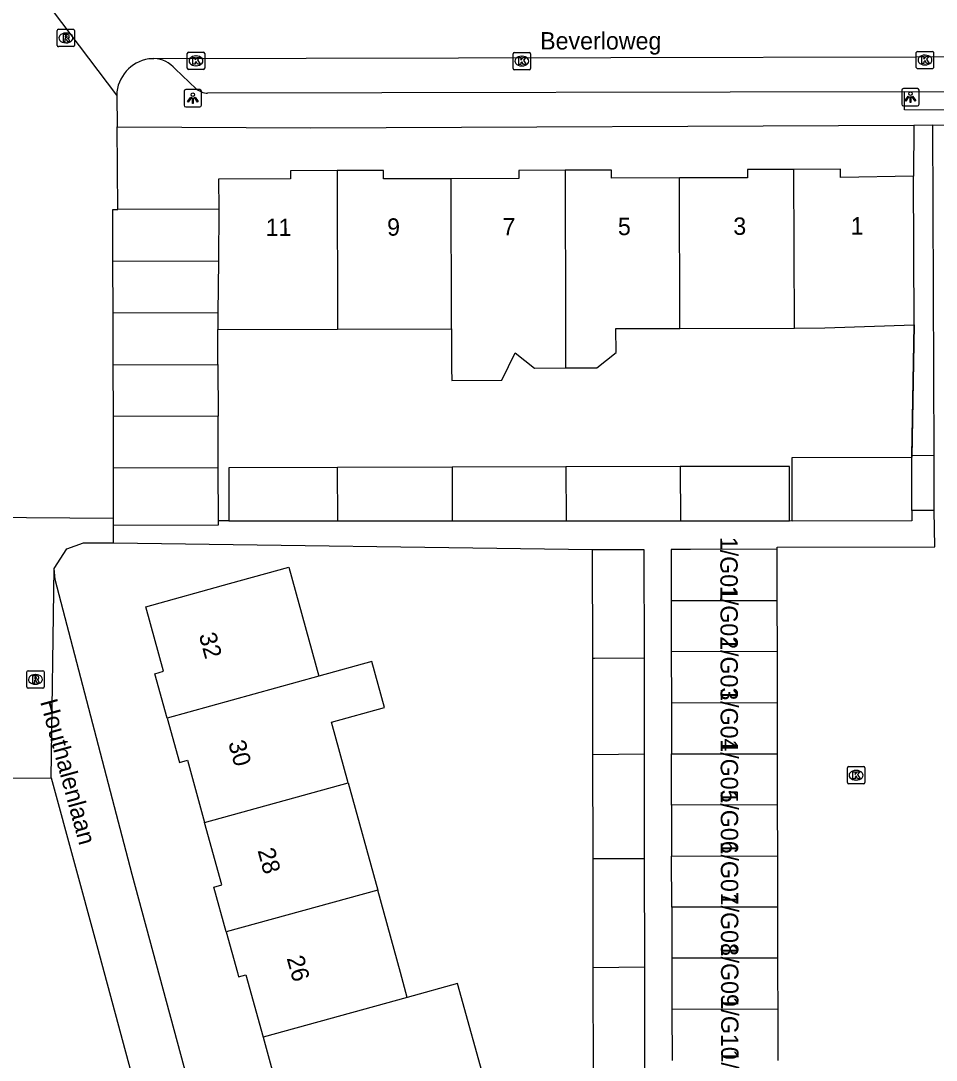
# Model space of a CAD drawing. Extents: x 160732 to 162105, y 387428 to 388479.
# Drawn here: x 161070.4 to 161123.2, y 387994.9 to 388054.8 of the extents above; entities that cross this region are included whole.
import ezdxf

# ---------------------------------------------------------------- set-up
doc = ezdxf.new("R2010")
doc.units = 0
for name, color, linetype in [('IMGEO_Kolk', 7, 'Continuous'), ('IMGEO_Lichtpunt', 7, 'Continuous'), ('IMGEO_Muur', 7, 'Continuous'), ('IMGEO_Openbare_ruimte_label', 7, 'Continuous'), ('IMGEO_Pand', 7, 'Continuous'), ('IMGEO_Pand_nummerreeks', 7, 'Continuous'), ('IMGEO_Rijbaan_lokaal_open', 7, 'Continuous'), ('IMGEO_Rioolput', 7, 'Continuous'), ('IMGEO_Voetpad_open', 7, 'Continuous')]:
    doc.layers.add(name, color=color, linetype=linetype)

msp = doc.modelspace()

# ---------------------------------------------------------------- linework, layer by layer
at = {"layer": 'IMGEO_Kolk'}
for p, q in [((161080.006, 388052.075), (161080.006, 388052.927)), ((161080.081, 388053.001), (161080.933, 388053.001)), ((161080.494, 388052.781), (161080.519, 388052.781)), ((161081.007, 388052.927), (161081.007, 388052.075)), ((161098.78, 388052.061), (161098.78, 388052.913)), ((161098.855, 388052.987), (161099.707, 388052.987)), ((161099.268, 388052.767), (161099.293, 388052.767)), ((161099.781, 388052.913), (161099.781, 388052.061)), ((161122.012, 388052.121), (161122.012, 388052.973)), ((161122.087, 388053.047), (161122.939, 388053.047)), ((161122.5, 388052.827), (161122.525, 388052.827)), ((161123.013, 388052.973), (161123.013, 388052.121)), ((161080.933, 388052.001), (161080.081, 388052.001)), ((161080.517, 388052.221), (161080.492, 388052.221)), ((161099.707, 388051.987), (161098.855, 388051.987)), ((161099.291, 388052.207), (161099.266, 388052.207)), ((161122.939, 388052.047), (161122.087, 388052.047)), ((161122.523, 388052.267), (161122.498, 388052.267)), ((161118.04, 388010.929), (161118.04, 388011.781)), ((161118.115, 388011.855), (161118.967, 388011.855)), ((161119.041, 388011.781), (161119.041, 388010.929)), ((161118.528, 388011.635), (161118.553, 388011.635)), ((161118.967, 388010.855), (161118.115, 388010.855)), ((161118.551, 388011.075), (161118.526, 388011.075))]:
    msp.add_line(p, q, dxfattribs=at)
for points in [[(161080.006, 388052.075), (161080.006, 388052.927)], [(161080.081, 388053.001), (161080.933, 388053.001)], [(161080.327, 388052.701), (161080.45, 388052.701), (161080.45, 388052.55), (161080.58, 388052.701), (161080.744, 388052.701), (161080.598, 388052.55), (161080.751, 388052.301), (161080.599, 388052.301), (161080.514, 388052.465), (161080.45, 388052.398), (161080.45, 388052.301), (161080.327, 388052.301), (161080.327, 388052.701)], [(161081.007, 388052.927), (161081.007, 388052.075)], [(161098.78, 388052.061), (161098.78, 388052.913)], [(161098.855, 388052.987), (161099.707, 388052.987)], [(161099.101, 388052.687), (161099.224, 388052.687), (161099.224, 388052.536), (161099.354, 388052.687), (161099.518, 388052.687), (161099.372, 388052.536), (161099.525, 388052.287), (161099.373, 388052.287), (161099.288, 388052.451), (161099.224, 388052.384), (161099.224, 388052.287), (161099.101, 388052.287), (161099.101, 388052.687)], [(161099.781, 388052.913), (161099.781, 388052.061)], [(161122.012, 388052.121), (161122.012, 388052.973)], [(161122.087, 388053.047), (161122.939, 388053.047)], [(161122.333, 388052.747), (161122.456, 388052.747), (161122.456, 388052.596), (161122.586, 388052.747), (161122.75, 388052.747), (161122.604, 388052.596), (161122.757, 388052.347), (161122.605, 388052.347), (161122.52, 388052.511), (161122.456, 388052.444), (161122.456, 388052.347), (161122.333, 388052.347), (161122.333, 388052.747)], [(161123.013, 388052.973), (161123.013, 388052.121)], [(161080.933, 388052.001), (161080.081, 388052.001)], [(161099.707, 388051.987), (161098.855, 388051.987)], [(161122.939, 388052.047), (161122.087, 388052.047)], [(161118.04, 388010.929), (161118.04, 388011.781)], [(161118.115, 388011.855), (161118.967, 388011.855)], [(161119.041, 388011.781), (161119.041, 388010.929)], [(161118.361, 388011.555), (161118.484, 388011.555), (161118.484, 388011.404), (161118.614, 388011.555), (161118.778, 388011.555), (161118.632, 388011.404), (161118.785, 388011.155), (161118.633, 388011.155), (161118.548, 388011.319), (161118.484, 388011.252), (161118.484, 388011.155), (161118.361, 388011.155), (161118.361, 388011.555)], [(161118.967, 388010.855), (161118.115, 388010.855)]]:
    msp.add_lwpolyline(points, dxfattribs=at)
for centre, start, end in [((161080.083, 388052.925), 91.55205, 178.44795), ((161080.083, 388052.925), 91.55205, 178.44795), ((161080.931, 388052.925), 1.55205, 88.44795), ((161080.931, 388052.925), 1.55205, 88.44795), ((161098.857, 388052.911), 91.55205, 178.44795), ((161098.857, 388052.911), 91.55205, 178.44795), ((161099.705, 388052.911), 1.55205, 88.44795), ((161099.705, 388052.911), 1.55205, 88.44795), ((161122.089, 388052.971), 91.55205, 178.44795), ((161122.089, 388052.971), 91.55205, 178.44795), ((161122.937, 388052.971), 1.55205, 88.44795), ((161122.937, 388052.971), 1.55205, 88.44795), ((161080.083, 388052.077), 181.55205, 268.44795), ((161080.083, 388052.077), 181.55205, 268.44795), ((161080.931, 388052.077), 271.55205, 358.44795), ((161080.931, 388052.077), 271.55205, 358.44795), ((161098.857, 388052.063), 181.55205, 268.44795), ((161098.857, 388052.063), 181.55205, 268.44795), ((161099.705, 388052.063), 271.55205, 358.44795), ((161099.705, 388052.063), 271.55205, 358.44795), ((161122.089, 388052.123), 181.55205, 268.44795), ((161122.089, 388052.123), 181.55205, 268.44795), ((161122.937, 388052.123), 271.55205, 358.44795), ((161122.937, 388052.123), 271.55205, 358.44795), ((161118.117, 388011.779), 91.55205, 178.44795), ((161118.117, 388011.779), 91.55205, 178.44795), ((161118.965, 388011.779), 1.55205, 88.44795), ((161118.965, 388011.779), 1.55205, 88.44795), ((161118.117, 388010.931), 181.55205, 268.44795), ((161118.117, 388010.931), 181.55205, 268.44795), ((161118.965, 388010.931), 271.55205, 358.44795), ((161118.965, 388010.931), 271.55205, 358.44795)]:
    msp.add_arc(centre, 0.0765, start, end, dxfattribs=at)
for centre, major_axis, ratio, start_param, end_param in [((161080.493, 388052.501), (-0.387, 0.002), 0.722429, 4.712389, 7.853982), ((161080.518, 388052.501), (-0.39, 0.002), 0.717154, 1.570796, 4.712389), ((161099.267, 388052.487), (-0.387, 0.002), 0.722429, 4.712389, 7.853982), ((161099.292, 388052.487), (-0.39, 0.002), 0.717154, 1.570796, 4.712389), ((161122.499, 388052.547), (-0.387, 0.002), 0.722429, 4.712389, 7.853982), ((161122.524, 388052.547), (-0.39, 0.002), 0.717154, 1.570796, 4.712389), ((161118.527, 388011.355), (-0.387, 0.002), 0.722429, 4.712389, 7.853982), ((161118.552, 388011.355), (-0.39, 0.002), 0.717154, 1.570796, 4.712389)]:
    msp.add_ellipse(centre, major_axis=major_axis, ratio=ratio, start_param=start_param, end_param=end_param, dxfattribs=at)
at = {"layer": 'IMGEO_Lichtpunt'}
for p, q in [((161079.826, 388050.751), (161079.826, 388049.944)), ((161079.826, 388050.751), (161079.826, 388049.944)), ((161080.728, 388050.846), (161079.92, 388050.846)), ((161080.728, 388050.846), (161079.92, 388050.846)), ((161080.822, 388049.944), (161080.822, 388050.751)), ((161080.822, 388049.944), (161080.822, 388050.751)), ((161121.178, 388050.809), (161121.178, 388050.002)), ((161121.178, 388050.809), (161121.178, 388050.002)), ((161122.08, 388050.904), (161121.272, 388050.904)), ((161122.08, 388050.904), (161121.272, 388050.904)), ((161122.174, 388050.002), (161122.174, 388050.809)), ((161122.174, 388050.002), (161122.174, 388050.809)), ((161079.92, 388049.85), (161080.728, 388049.85)), ((161079.92, 388049.85), (161080.728, 388049.85)), ((161121.272, 388049.908), (161122.08, 388049.908)), ((161121.272, 388049.908), (161122.08, 388049.908))]:
    msp.add_line(p, q, dxfattribs=at)
for points in [[(161080.2, 388050.415), (161080.239, 388050.387), (161080.051, 388050.125), (161080.013, 388050.152), (161080.2, 388050.415)], [(161080.302, 388050.367), (161080.349, 388050.367), (161080.349, 388050.045), (161080.302, 388050.045), (161080.302, 388050.367)], [(161080.412, 388050.387), (161080.45, 388050.414), (161080.637, 388050.152), (161080.598, 388050.124), (161080.412, 388050.387)], [(161121.552, 388050.473), (161121.591, 388050.445), (161121.403, 388050.183), (161121.365, 388050.21), (161121.552, 388050.473)], [(161121.654, 388050.425), (161121.701, 388050.425), (161121.701, 388050.103), (161121.654, 388050.103), (161121.654, 388050.425)], [(161121.764, 388050.445), (161121.802, 388050.472), (161121.989, 388050.21), (161121.95, 388050.182), (161121.764, 388050.445)]]:
    msp.add_lwpolyline(points, dxfattribs=at)
for centre in [(161121.677, 388050.607), (161080.325, 388050.549)]:
    msp.add_circle(centre, 0.0994, dxfattribs=at)
for centre, start, end in [((161079.92, 388050.751), 90, 180), ((161079.92, 388050.751), 90, 180), ((161080.728, 388050.751), 0, 90), ((161080.728, 388050.751), 0, 90), ((161121.272, 388050.809), 90, 180), ((161121.272, 388050.809), 90, 180), ((161122.08, 388050.809), 0, 90), ((161122.08, 388050.809), 0, 90), ((161079.92, 388049.944), 180, 270), ((161079.92, 388049.944), 180, 270), ((161080.728, 388049.944), 270, 0), ((161080.728, 388049.944), 270, 360), ((161121.272, 388050.002), 180, 270), ((161121.272, 388050.002), 180, 270), ((161122.08, 388050.002), 270, 0), ((161122.08, 388050.002), 270, 360)]:
    msp.add_arc(centre, 0.0946, start, end, dxfattribs=at)
at = {"layer": 'IMGEO_Muur'}
msp.add_lwpolyline([(161121.887, 388037.296), (161121.748, 388029.67)], dxfattribs=at)
at = {"layer": 'IMGEO_Pand'}
for points in [[(161088.638, 388046.18), (161085.96, 388046.173), (161085.962, 388045.696), (161081.813, 388045.685), (161081.817, 388043.949)], [(161095.21, 388045.713), (161091.314, 388045.702), (161091.313, 388046.187), (161088.638, 388046.18)], [(161088.638, 388046.18), (161088.655, 388037.038)], [(161101.775, 388046.196), (161099.103, 388046.189), (161099.105, 388045.724), (161095.21, 388045.713)], [(161108.368, 388045.755), (161104.447, 388045.744), (161104.446, 388046.203), (161101.775, 388046.196)], [(161101.775, 388046.196), (161101.8, 388037.073), (161101.806, 388034.81)], [(161114.962, 388046.248), (161112.287, 388046.241), (161112.289, 388045.765), (161108.368, 388045.755)], [(161121.85, 388045.854), (161117.64, 388045.772), (161117.639, 388046.256), (161114.962, 388046.248)], [(161114.987, 388037.109), (161114.962, 388046.248)], [(161095.232, 388037.056), (161095.238, 388037.056), (161095.21, 388045.713)], [(161108.39, 388037.091), (161108.368, 388045.755)], [(161121.887, 388037.296), (161121.85, 388045.854)], [(161075.719, 388040.953), (161075.711, 388043.932), (161075.997, 388043.933)], [(161081.817, 388043.949), (161075.997, 388043.933)], [(161081.817, 388043.949), (161081.796, 388040.969)], [(161081.796, 388040.969), (161075.719, 388040.953)], [(161075.727, 388037.974), (161075.719, 388040.953)], [(161081.796, 388040.969), (161081.774, 388037.99)], [(161081.774, 388037.99), (161075.727, 388037.974)], [(161075.736, 388034.995), (161075.727, 388037.974)], [(161081.774, 388037.99), (161081.767, 388037.019)], [(161081.767, 388037.019), (161088.655, 388037.038)], [(161081.773, 388035.011), (161081.767, 388037.019)], [(161088.655, 388037.038), (161095.232, 388037.056)], [(161095.232, 388037.056), (161095.238, 388034.793), (161095.24, 388034.098), (161098.135, 388034.106), (161098.899, 388035.685), (161100.011, 388034.806), (161101.806, 388034.81)], [(161101.806, 388034.81), (161103.601, 388034.815), (161104.71, 388035.698), (161104.707, 388037.081), (161108.39, 388037.091)], [(161108.39, 388037.091), (161114.987, 388037.109)], [(161114.987, 388037.109), (161116.733, 388037.114), (161121.887, 388037.296)], [(161075.736, 388034.995), (161081.773, 388035.011)], [(161075.744, 388032.015), (161075.736, 388034.995)], [(161081.773, 388035.011), (161081.781, 388032.032)], [(161081.781, 388032.032), (161075.744, 388032.015)], [(161075.752, 388029.036), (161075.744, 388032.015)], [(161081.789, 388029.053), (161081.781, 388032.032)], [(161114.704, 388026.006), (161114.704, 388029.146), (161108.41, 388029.128)], [(161114.856, 388025.992), (161114.851, 388029.662), (161121.748, 388029.67)], [(161121.751, 388026.608), (161121.748, 388029.67)], [(161081.789, 388029.053), (161075.752, 388029.036)], [(161075.76, 388026.15), (161075.752, 388029.036)], [(161081.797, 388026.007), (161081.789, 388029.053)], [(161088.67, 388029.072), (161082.39, 388029.055), (161082.39, 388026.009)], [(161095.264, 388029.091), (161088.67, 388029.072)], [(161088.676, 388026.008), (161088.67, 388029.072)], [(161101.821, 388029.109), (161095.264, 388029.091)], [(161095.264, 388029.091), (161095.274, 388026.008)], [(161108.41, 388029.128), (161101.821, 388029.109)], [(161101.821, 388029.109), (161101.83, 388026.007)], [(161108.41, 388029.128), (161108.418, 388026.007)], [(161075.761, 388025.766), (161075.76, 388026.15)], [(161121.751, 388026.608), (161121.752, 388026.001), (161114.856, 388025.992)], [(161075.761, 388025.766), (161081.798, 388025.783), (161081.797, 388026.007)], [(161082.39, 388026.009), (161088.676, 388026.008)], [(161088.676, 388026.008), (161095.274, 388026.008)], [(161095.274, 388026.008), (161101.83, 388026.007)], [(161101.83, 388026.007), (161108.418, 388026.007)], [(161108.418, 388026.007), (161114.704, 388026.006)], [(161103.358, 388024.352), (161106.313, 388024.357), (161106.322, 388018.09)], [(161103.367, 388018.084), (161103.358, 388024.352)], [(161113.998, 388024.367), (161108.999, 388024.358), (161107.886, 388024.356), (161107.891, 388021.413)], [(161114.003, 388021.424), (161113.998, 388024.367)], [(161078.841, 388014.648), (161078.137, 388017.204), (161078.633, 388017.341), (161077.607, 388021.063), (161082.428, 388022.393), (161085.849, 388023.336), (161087.58, 388017.057)], [(161107.891, 388021.413), (161114.003, 388021.424)], [(161107.891, 388021.413), (161107.896, 388018.47)], [(161114.008, 388018.48), (161114.003, 388021.424)], [(161114.008, 388018.48), (161107.896, 388018.47)], [(161107.896, 388018.47), (161107.901, 388015.526)], [(161114.013, 388015.537), (161114.008, 388018.48)], [(161089.274, 388010.911), (161088.308, 388014.416), (161091.374, 388015.261), (161090.646, 388017.902), (161087.58, 388017.057)], [(161106.322, 388018.09), (161103.461, 388018.085), (161103.367, 388018.084)], [(161103.375, 388012.521), (161103.367, 388018.084)], [(161106.322, 388018.09), (161106.33, 388012.56)], [(161087.58, 388017.057), (161078.841, 388014.648)], [(161107.901, 388015.526), (161114.013, 388015.537)], [(161107.901, 388015.526), (161107.906, 388012.583)], [(161114.018, 388012.594), (161114.013, 388015.537)], [(161078.841, 388014.648), (161079.547, 388012.089), (161080.017, 388012.219), (161081.006, 388008.63)], [(161106.33, 388012.56), (161103.375, 388012.521)], [(161103.384, 388006.557), (161103.375, 388012.521)], [(161106.33, 388012.56), (161106.339, 388006.563)], [(161107.906, 388012.583), (161114.018, 388012.594)], [(161107.911, 388009.64), (161107.906, 388012.583)], [(161114.023, 388009.65), (161114.018, 388012.594)], [(161081.006, 388008.63), (161089.274, 388010.911)], [(161089.274, 388010.911), (161090.978, 388004.731)], [(161114.023, 388009.65), (161107.911, 388009.64)], [(161107.911, 388009.64), (161107.916, 388006.696)], [(161114.028, 388006.707), (161114.023, 388009.65)], [(161082.25, 388002.332), (161081.539, 388004.914), (161081.996, 388005.04), (161081.006, 388008.63)], [(161103.384, 388006.557), (161103.481, 388006.558), (161106.339, 388006.563)], [(161103.394, 388000.283), (161103.384, 388006.557)], [(161106.339, 388006.563), (161106.348, 388000.312)], [(161107.916, 388006.696), (161114.028, 388006.707)], [(161107.922, 388003.753), (161107.916, 388006.696)], [(161114.034, 388003.764), (161114.028, 388006.707)], [(161090.978, 388004.731), (161082.25, 388002.332)], [(161092.671, 387998.562), (161092.282, 388000), (161090.978, 388004.731)], [(161114.034, 388003.764), (161107.922, 388003.753)], [(161107.922, 388003.753), (161107.927, 388000.81)], [(161114.039, 388000.82), (161114.034, 388003.764)], [(161082.25, 388002.332), (161082.893, 388000), (161082.962, 387999.751), (161083.377, 387999.865), (161084.368, 387996.27)], [(161114.039, 388000.82), (161107.927, 388000.81)], [(161107.927, 388000.81), (161107.928, 388000), (161107.932, 387997.866)], [(161114.044, 387997.877), (161114.04, 388000), (161114.039, 388000.82)], [(161103.394, 388000.283), (161106.348, 388000.312)], [(161103.403, 387993.824), (161103.394, 388000.283)], [(161106.348, 388000.312), (161106.358, 387993.829)], [(161094.369, 387992.408), (161097.28, 387993.211), (161095.583, 387999.365), (161092.671, 387998.562)], [(161092.671, 387998.562), (161084.368, 387996.27)], [(161114.044, 387997.877), (161107.932, 387997.866)], [(161107.932, 387997.866), (161107.937, 387994.923)], [(161114.049, 387994.933), (161114.044, 387997.877)], [(161084.368, 387996.27), (161085.359, 387992.673), (161084.902, 387992.547), (161085.607, 387989.99)]]:
    msp.add_lwpolyline(points, dxfattribs=at)
at = {"layer": 'IMGEO_Rijbaan_lokaal_open'}
for points in [[(161075.936, 388050.523), (161070.621, 388057.563)], [(161078.086, 388052.625), (161077.784, 388052.607)], [(161148.324, 388052.768), (161078.086, 388052.625)], [(161075.76, 388026.15), (161068.202, 388026.2), (161068.137, 388045.744), (161068.122, 388050.436)], [(161075.936, 388050.523), (161075.962, 388048.699)], [(161075.997, 388043.933), (161075.962, 388048.699)], [(161121.867, 388048.795), (161121.85, 388045.854)], [(161121.867, 388048.795), (161122.971, 388048.812)], [(161123.033, 388029.762), (161122.971, 388048.812)], [(161122.971, 388048.812), (161127.744, 388048.8)], [(161121.749, 388029.752), (161121.887, 388037.296)], [(161123.033, 388029.762), (161121.749, 388029.752)], [(161123.034, 388026.607), (161123.033, 388029.762)], [(161113.998, 388024.367), (161113.998, 388024.499), (161123.084, 388024.511), (161123.034, 388026.607)]]:
    msp.add_lwpolyline(points, dxfattribs=at)
msp.add_arc((161078.117, 388050.451), 2.182, 98.77169, 178.09789, dxfattribs=at)
at = {"layer": 'IMGEO_Rioolput'}
for p, q in [((161072.587, 388054.317), (161073.439, 388054.317)), ((161072.512, 388053.391), (161072.512, 388054.243)), ((161073, 388054.097), (161073.025, 388054.097)), ((161073.513, 388054.243), (161073.513, 388053.391)), ((161073.439, 388053.317), (161072.587, 388053.317)), ((161073.023, 388053.537), (161072.998, 388053.537)), ((161070.752, 388016.45), (161070.752, 388017.302)), ((161070.827, 388017.376), (161071.679, 388017.376)), ((161071.753, 388017.302), (161071.753, 388016.45)), ((161071.263, 388016.596), (161071.238, 388016.596)), ((161071.24, 388017.156), (161071.265, 388017.156)), ((161071.679, 388016.376), (161070.827, 388016.376))]:
    msp.add_line(p, q, dxfattribs=at)
for points in [[(161072.587, 388054.317), (161073.439, 388054.317)], [(161072.512, 388053.391), (161072.512, 388054.243)], [(161073.101, 388054.015), (161072.849, 388054.017), (161072.849, 388053.617)], [(161072.849, 388053.617), (161072.973, 388053.617), (161072.973, 388053.779), (161072.984, 388053.779)], [(161073.027, 388053.936), (161072.973, 388053.936), (161072.973, 388053.855)], [(161072.973, 388053.855), (161073.025, 388053.855)], [(161073.031, 388053.75), (161073.102, 388053.617), (161073.242, 388053.617), (161073.177, 388053.743)], [(161073.513, 388054.243), (161073.513, 388053.391)], [(161073.439, 388053.317), (161072.587, 388053.317)], [(161070.752, 388016.45), (161070.752, 388017.302)], [(161070.827, 388017.376), (161071.679, 388017.376)], [(161071.753, 388017.302), (161071.753, 388016.45)], [(161071.341, 388017.074), (161071.089, 388017.076), (161071.089, 388016.676)], [(161071.089, 388016.676), (161071.213, 388016.676), (161071.213, 388016.838), (161071.224, 388016.838)], [(161071.267, 388016.995), (161071.213, 388016.995), (161071.213, 388016.914)], [(161071.213, 388016.914), (161071.265, 388016.914)], [(161071.271, 388016.809), (161071.342, 388016.676), (161071.482, 388016.676), (161071.417, 388016.802)], [(161071.679, 388016.376), (161070.827, 388016.376)]]:
    msp.add_lwpolyline(points, dxfattribs=at)
for centre, radius, start, end in [((161072.589, 388054.241), 0.0765, 91.55205, 178.44795), ((161072.589, 388054.241), 0.0765, 91.55205, 178.44795), ((161073.437, 388054.241), 0.0765, 1.55205, 88.44795), ((161073.437, 388054.241), 0.0765, 1.55205, 88.44795), ((161072.983, 388053.726), 0.0533, 26.02933, 88.69889), ((161073.009, 388054.044), 0.19, 274.7715, 282.96867), ((161073.033, 388053.84), 0.0964, 77.00612, 93.18647), ((161073.047, 388053.897), 0.0378, 276.66336, 79.67722), ((161073.1, 388053.905), 0.109, 350.36119, 89.41601), ((161073.098, 388053.905), 0.112, 277.58423, 350.98172), ((161073.082, 388053.69), 0.108, 29.51342, 73.79051), ((161072.589, 388053.393), 0.0765, 181.55205, 268.44795), ((161072.589, 388053.393), 0.0765, 181.55205, 268.44795), ((161073.437, 388053.393), 0.0765, 271.55205, 358.44795), ((161073.437, 388053.393), 0.0765, 271.55205, 358.44795), ((161070.829, 388017.3), 0.0765, 91.55205, 178.44795), ((161070.829, 388017.3), 0.0765, 91.55205, 178.44795), ((161071.677, 388017.3), 0.0765, 1.55205, 88.44795), ((161071.677, 388017.3), 0.0765, 1.55205, 88.44795), ((161071.223, 388016.785), 0.0533, 26.02933, 88.69889), ((161071.249, 388017.103), 0.19, 274.7715, 282.96867), ((161071.273, 388016.899), 0.0964, 77.00612, 93.18647), ((161071.287, 388016.956), 0.0378, 276.66336, 79.67722), ((161071.34, 388016.964), 0.109, 350.36119, 89.41601), ((161071.338, 388016.964), 0.112, 277.58423, 350.98172), ((161071.322, 388016.749), 0.108, 29.51342, 73.79051), ((161070.829, 388016.452), 0.0765, 181.55205, 268.44795), ((161070.829, 388016.452), 0.0765, 181.55205, 268.44795), ((161071.677, 388016.452), 0.0765, 271.55205, 358.44795), ((161071.677, 388016.452), 0.0765, 271.55205, 358.44795)]:
    msp.add_arc(centre, radius, start, end, dxfattribs=at)
for centre, major_axis, ratio, start_param, end_param in [((161072.999, 388053.817), (-0.387, 0.002), 0.722429, 4.712389, 7.853982), ((161073.024, 388053.817), (-0.39, 0.002), 0.717154, 1.570796, 4.712389), ((161071.239, 388016.876), (-0.387, 0.002), 0.722429, 4.712389, 7.853982), ((161071.264, 388016.876), (-0.39, 0.002), 0.717154, 1.570796, 4.712389)]:
    msp.add_ellipse(centre, major_axis=major_axis, ratio=ratio, start_param=start_param, end_param=end_param, dxfattribs=at)
at = {"layer": 'IMGEO_Voetpad_open'}
for points in [[(161080.525, 388050.896), (161079.302, 388052.031)], [(161121.327, 388050.719), (161081.174, 388050.641)], [(161121.327, 388050.719), (161134.265, 388050.758)], [(161134.265, 388050.758), (161134.284, 388049.621), (161121.329, 388049.67), (161121.327, 388050.719)], [(161075.962, 388048.699), (161087.123, 388048.639), (161121.867, 388048.795)], [(161121.748, 388029.67), (161121.749, 388029.752)], [(161123.034, 388026.607), (161121.751, 388026.608)], [(161075.745, 388024.742), (161075.761, 388025.766)], [(161082.39, 388026.009), (161081.797, 388026.007)], [(161114.856, 388025.992), (161114.704, 388026.006)], [(161072.336, 388023.268), (161073.073, 388024.393), (161074.034, 388024.737), (161075.745, 388024.742)], [(161075.745, 388024.742), (161103.358, 388024.352)], [(161072.165, 388011.204), (161072.336, 388023.268)], [(161088.824, 387961.322), (161076.822, 388005.641), (161072.396, 388022.629), (161072.336, 388023.268)], [(161065.201, 388011.196), (161072.165, 388011.204)], [(161072.165, 388011.204), (161074.8, 388001.542), (161079.158, 387985.38), (161085.039, 387963.643)]]:
    msp.add_lwpolyline(points, dxfattribs=at)
for centre, radius, start, end in [((161078.058, 388051.027), 1.599, 38.9236, 89.0066), ((161081.18, 388051.61), 0.969, 227.459, 269.64006)]:
    msp.add_arc(centre, radius, start, end, dxfattribs=at)

# ---------------------------------------------------------------- texts
at = {"layer": 'IMGEO_Openbare_ruimte_label'}
msp.add_text('Beverloweg', height=1, dxfattribs=at).set_placement((161100.337, 388053.154))
msp.add_text('Houthalenlaan', height=1, rotation=285.30032, dxfattribs=at).set_placement((161071.52, 388015.589))
at = {"layer": 'IMGEO_Pand_nummerreeks'}
for s, rotation, p in [('11', 0.14218, (161084.525, 388042.411)), ('9', 0.14324, (161091.52, 388042.429)), ('7', 0.14324, (161098.17, 388042.445)), ('5', 0.14324, (161104.819, 388042.462)), ('3', 0.14218, (161111.468, 388042.478)), ('1', 0.14218, (161118.232, 388042.496)), ('1/G01', 270.09876, (161110.717, 388025.087)), ('1/G02', 270.09876, (161110.722, 388022.26)), ('32', 285.25296, (161080.665, 388019.428)), ('1/G03', 270.09876, (161110.727, 388019.31)), ('1/G04', 270.09876, (161110.732, 388016.367)), ('30', 285.25296, (161082.357, 388013.224)), ('1/G05', 270.09876, (161110.737, 388013.424)), ('1/G06', 270.09876, (161110.742, 388010.48)), ('28', 285.25296, (161084.047, 388007.025)), ('1/G07', 270.09876, (161110.747, 388007.537)), ('1/G08', 270.09876, (161110.752, 388004.59)), ('1/G09', 270.09869, (161110.757, 388001.653)), ('26', 285.47613, (161085.724, 388000.823)), ('1/G10', 270.09867, (161110.762, 387998.612)), ('1/G11', 270.09867, (161110.768, 387995.562))]:
    msp.add_text(s, height=1, rotation=rotation, dxfattribs=at).set_placement(p)

doc.saveas('drawing.dxf')
